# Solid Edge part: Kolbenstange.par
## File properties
Username: bmolnar
Dokumentum tartalom típus: 0
Author: bmolnar
Last saved by: bmolnar
Revision: 83
Sűrűség: 0,000 kg/m^3
Pontosság: 0,990
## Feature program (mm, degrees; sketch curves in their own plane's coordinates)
base feature "unnamed BaseFeature 1"
sketch for "unnamed Protrusion 1" plane through (39.2, 0, 0) normal (1, 0, 0) x-axis (0, 0, -1)
  circle centre (0, 0) radius 25
extrude "unnamed Protrusion 1" add finite 17.6 along +normal
sketch for "Kihúzás_2" #1 plane through (39.2, 0, 0) normal (1, 0, 0) x-axis (0, 0, -1)
  circle centre (0, 0) radius 8
sketch for "Kihúzás_2" #2 plane through (39.2, 0, 0) normal (1, 0, 0) x-axis (0, 0, -1)
  circle centre (0, 0) radius 25
extrude "Kihúzás_2" add finite 9.4 along -normal
sketch for "Furat_1" plane through (-27, 0, 0.0012) normal (-1, 0, 0) x-axis (0, 0, 1)
  hole centre (-0.0012, 0) bore radius 3.3235
hole "Furat_1" nominal diameter 8 finite  VBottomAngle = 118 deg; ThreadDepth = 14 mm
chamfer "Letörés_1" setback 0.7  SetBackValue2 = 45 deg
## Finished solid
Body 1: solid body, 16 faces, 22 edges, 8 vertices.
  Faces by surface: plane 8, cylinder 5, cone 2, torus 1
  Edges by curve: circle 12, line 6, curve on surface 2, ellipse 2
Bounding box of the edges (mm; curved faces can reach further): 86.800 x 50.000 x 50.000, from (-30, -25, -25) to (56.8, 25, 25).
Cylindrical faces by radius (mm): R3.3235 x2, R4.125 x1, R8 x1, R25 x1
Conical faces (half-angle, radius in mm at the cone's reference point): 45 deg R4.0235 x1, 59 deg R3.3235 x1
Toroidal faces (ring radius, tube radius in mm): R6.2 r1.8 x1
Planar faces by outward normal: +x 1, +y 1, -x 3, -y 1, oblique 2
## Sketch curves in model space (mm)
circle centre (39.2, 0, 0) radius 25
circle centre (39.2, 0, 0) radius 8
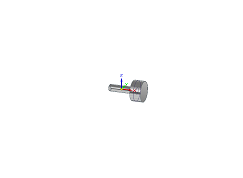
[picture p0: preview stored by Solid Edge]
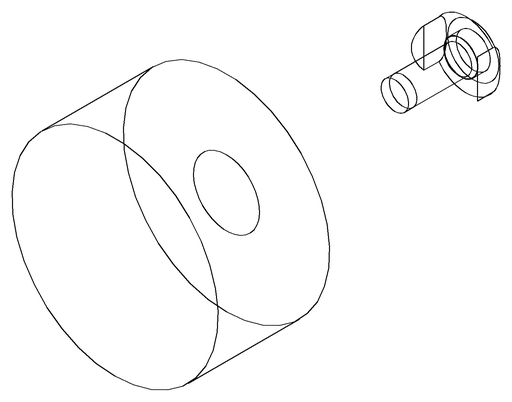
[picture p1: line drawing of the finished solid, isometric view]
